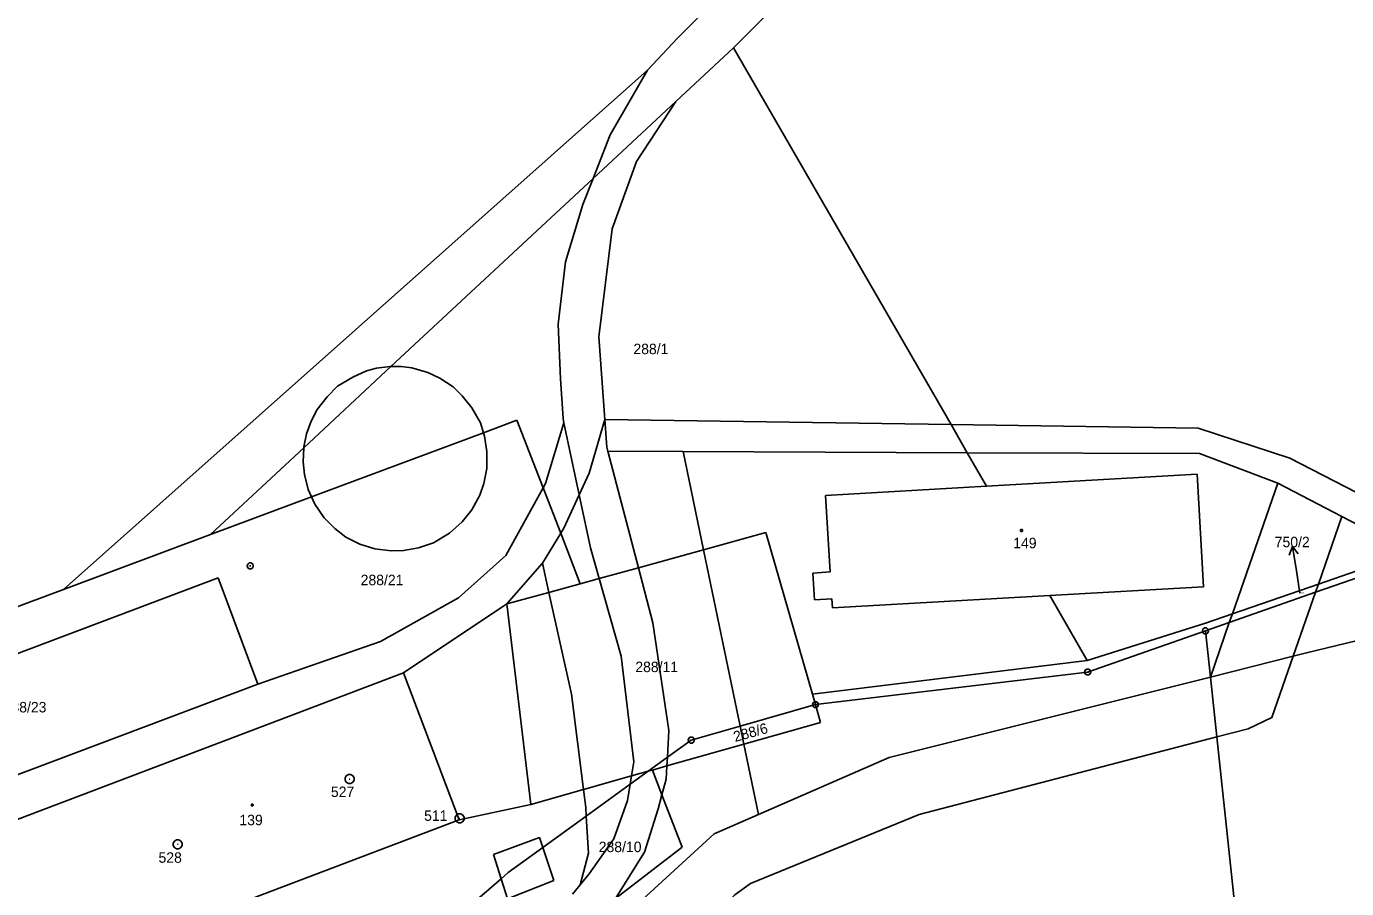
# Model space of a CAD drawing. Extents: x -694465 to -690527, y -983694 to -978978.
# Drawn here: x -693381.2 to -693166.5, y -981277 to -981137 of the extents above; entities that cross this region are included whole.
import ezdxf

# ---------------------------------------------------------------- set-up
doc = ezdxf.new("R2010")
doc.units = 0
for name, color, linetype in [('Vrstva 1', 7, 'Continuous'), ('Vrstva 16', 7, 'Continuous'), ('Vrstva 17', 7, 'Continuous'), ('Vrstva 18', 7, 'Continuous'), ('Vrstva 19', 7, 'Continuous'), ('Vrstva 24', 7, 'Continuous'), ('Vrstva 25', 7, 'Continuous'), ('Vrstva 29', 7, 'Continuous')]:
    doc.layers.add(name, color=color, linetype=linetype)

msp = doc.modelspace()

# ---------------------------------------------------------------- linework, layer by layer
at = {"layer": 'Vrstva 1'}
for points in [[(-693280.193, -981144.086), (-693275.377, -981138.931), (-693243.869, -981107.405), (-693240.17, -981100.71)], [(-693266.21, -981140.43), (-693233.406, -981107.461)], [(-693275.612, -981149.175), (-693266.21, -981140.43)], [(-693230.844, -981201.655), (-693266.21, -981140.43)], [(-693280.193, -981144.086), (-693375.15, -981228.43)], [(-693289.022, -981161.649), (-693286.252, -981154.594), (-693280.193, -981144.086)], [(-693289.022, -981161.649), (-693275.612, -981149.175)], [(-693287.127, -981200.804), (-693288.109, -981187.376), (-693285.917, -981169.842), (-693281.972, -981158.883), (-693275.612, -981149.175)], [(-693321.909, -981192.238), (-693289.022, -981161.649)], [(-693293.777, -981201.381), (-693293.927, -981200.67), (-693294.331, -981194.204), (-693294.735, -981185.312), (-693293.523, -981175.207), (-693290.696, -981165.911), (-693289.022, -981161.649)], [(-693336.077, -981205.416), (-693321.909, -981192.238)], [(-693325.879, -981192.903), (-693324.263, -981192.486), (-693322.057, -981192.239), (-693321.909, -981192.238)], [(-693321.909, -981192.238), (-693320.221, -981192.226), (-693318.482, -981192.41)], [(-693318.482, -981192.41), (-693315.906, -981193.178), (-693313.934, -981194.11), (-693311.797, -981195.535)], [(-693336.077, -981205.416), (-693336.071, -981205.294), (-693335.632, -981203.156), (-693334.865, -981201.073), (-693333.879, -981199.209), (-693332.29, -981197.125), (-693330.591, -981195.425), (-693328.126, -981193.945), (-693325.879, -981192.903)], [(-693311.797, -981195.535), (-693310.317, -981196.961), (-693308.728, -981198.934), (-693307.358, -981201.347), (-693306.869, -981202.981)], [(-693301.42, -981200.95), (-693306.869, -981202.981)], [(-693297.164, -981211.94), (-693301.42, -981200.95)], [(-693291.308, -981213.059), (-693289.7, -981209.56), (-693287.127, -981200.804)], [(-693230.844, -981201.655), (-693287.127, -981200.804)], [(-693286.625, -981205.993), (-693286.794, -981205.349), (-693287.127, -981200.804)], [(-693306.869, -981202.981), (-693334.805, -981213.394)], [(-693306.869, -981202.981), (-693306.701, -981203.54), (-693306.317, -981206.007), (-693306.317, -981208.803), (-693306.81, -981211.216), (-693307.468, -981213.135), (-693308.728, -981215.492), (-693310.317, -981217.466), (-693312.399, -981219.275), (-693314.975, -981220.865), (-693317.44, -981221.688), (-693319.851, -981222.126), (-693321.879, -981222.181), (-693324.509, -981221.852), (-693326.975, -981221.085), (-693329.221, -981219.933), (-693331.03, -981218.563), (-693332.783, -981216.808), (-693334.263, -981214.56), (-693334.805, -981213.394)], [(-693293.777, -981201.381), (-693296.77, -981211.226), (-693297.164, -981211.94)], [(-693291.308, -981213.059), (-693293.777, -981201.381)], [(-693228.204, -981206.224), (-693230.844, -981201.655)], [(-693152.637, -981218.409), (-693154.059, -981218.272), (-693175.759, -981207.087), (-693190.664, -981202.262), (-693230.844, -981201.655)], [(-693351.24, -981219.52), (-693336.077, -981205.416)], [(-693334.805, -981213.394), (-693335.358, -981212.203), (-693335.961, -981209.79), (-693336.18, -981207.707), (-693336.077, -981205.416)], [(-693274.382, -981206.042), (-693286.625, -981205.993)], [(-693281.676, -981224.918), (-693286.625, -981205.993)], [(-693228.204, -981206.224), (-693274.382, -981206.042)], [(-693274.382, -981206.042), (-693271.072, -981221.999)], [(-693225.07, -981211.65), (-693228.204, -981206.224)], [(-693190.444, -981206.373), (-693228.204, -981206.224)], [(-693190.444, -981206.373), (-693177.731, -981211.198)], [(-693251.23, -981213.15), (-693225.07, -981211.65)], [(-693190.81, -981209.69), (-693225.07, -981211.65)], [(-693189.77, -981228), (-693190.81, -981209.69)], [(-693177.731, -981211.198), (-693185.105, -981232.395)], [(-693177.731, -981211.198), (-693167.328, -981216.593)], [(-693334.805, -981213.394), (-693351.24, -981219.52)], [(-693297.164, -981211.94), (-693303.233, -981222.947), (-693310.908, -981229.818), (-693323.616, -981236.911), (-693343.52, -981243.82)], [(-693294.308, -981219.313), (-693297.164, -981211.94)], [(-693294.308, -981219.313), (-693293.808, -981218.5), (-693291.308, -981213.059)], [(-693288.07, -981226.678), (-693289.484, -981221.688), (-693291.308, -981213.059)], [(-693250.49, -981225.6), (-693251.23, -981213.15)], [(-693171.118, -981227.562), (-693167.328, -981216.593)], [(-693167.328, -981216.593), (-693156.15, -981222.39)], [(-693351.24, -981219.52), (-693375.15, -981228.43)], [(-693297.288, -981224.155), (-693294.308, -981219.313)], [(-693291.13, -981227.52), (-693294.308, -981219.313)], [(-693260.94, -981219.21), (-693271.072, -981221.999)], [(-693253.37, -981245.45), (-693260.94, -981219.21)], [(-693271.072, -981221.999), (-693281.676, -981224.918)], [(-693271.072, -981221.999), (-693265.13, -981250.647)], [(-693156.15, -981222.39), (-693171.118, -981227.562)], [(-693303.05, -981230.8), (-693297.315, -981224.198), (-693297.288, -981224.155)], [(-693296.229, -981228.923), (-693297.288, -981224.155)], [(-693171.597, -981228.897), (-693155.44, -981223.28)], [(-693405.77, -981247.58), (-693350.01, -981226.58)], [(-693350.01, -981226.58), (-693343.52, -981243.82)], [(-693288.07, -981226.678), (-693291.13, -981227.52)], [(-693281.676, -981224.918), (-693288.07, -981226.678)], [(-693282.787, -981258.751), (-693282.415, -981256.447), (-693284.499, -981239.282), (-693288.07, -981226.678)], [(-693276.953, -981255.718), (-693276.712, -981251.376), (-693279.342, -981233.842), (-693281.676, -981224.918)], [(-693253.29, -981225.77), (-693250.49, -981225.6)], [(-693253.04, -981230.14), (-693253.29, -981225.77)], [(-693375.15, -981228.43), (-693413.16, -981242.59)], [(-693296.229, -981228.923), (-693303.05, -981230.8)], [(-693291.13, -981227.52), (-693296.229, -981228.923)], [(-693290.598, -981260.957), (-693292.562, -981245.435), (-693296.229, -981228.923)], [(-693214.8, -981229.43), (-693189.77, -981228)], [(-693185.603, -981233.825), (-693171.597, -981228.897)], [(-693171.118, -981227.562), (-693185.105, -981232.395)], [(-693175.202, -981239.29), (-693171.597, -981228.897)], [(-693171.597, -981228.897), (-693171.118, -981227.562)], [(-693303.05, -981230.8), (-693319.84, -981241.99)], [(-693303.05, -981230.8), (-693299.18, -981263.38)], [(-693250.23, -981229.97), (-693253.04, -981230.14)], [(-693250.14, -981231.44), (-693250.23, -981229.97)], [(-693214.8, -981229.43), (-693250.14, -981231.44)], [(-693208.69, -981240.01), (-693214.8, -981229.43)], [(-693173.05, -981238.75), (-693137.37, -981230.15)], [(-693185.105, -981232.395), (-693189.46, -981233.9)], [(-693185.105, -981232.395), (-693185.603, -981233.825)], [(-693189.46, -981233.9), (-693208.69, -981240.01)], [(-693208.63, -981241.86), (-693189.48, -981235.18)], [(-693189.48, -981235.18), (-693185.603, -981233.825)], [(-693189.48, -981235.18), (-693188.68, -981242.67)], [(-693185.603, -981233.825), (-693188.68, -981242.67)], [(-693188.68, -981242.67), (-693175.202, -981239.29)], [(-693187.639, -981252.397), (-693182.55, -981251.063), (-693178.661, -981249.232), (-693175.202, -981239.29)], [(-693175.202, -981239.29), (-693173.05, -981238.75)], [(-693208.69, -981240.01), (-693253.37, -981245.45)], [(-693343.52, -981243.82), (-693399.28, -981264.81)], [(-693396.71, -981271.14), (-693319.84, -981241.99)], [(-693319.84, -981241.99), (-693310.8, -981265.85)], [(-693252.88, -981247.15), (-693208.63, -981241.86)], [(-693240.91, -981255.75), (-693188.68, -981242.67)], [(-693188.68, -981242.67), (-693187.639, -981252.397)], [(-693253.37, -981245.45), (-693252.88, -981247.15)], [(-693265.13, -981250.647), (-693252.88, -981247.15)], [(-693252.04, -981250.06), (-693252.88, -981247.15)], [(-693264.521, -981253.587), (-693252.04, -981250.06)], [(-693283.73, -981293.672), (-693275.124, -981286.967), (-693265.973, -981278.041), (-693263.457, -981276.21), (-693236.006, -981264.995), (-693187.639, -981252.397)], [(-693273.09, -981252.92), (-693265.13, -981250.647)], [(-693265.13, -981250.647), (-693264.521, -981253.587)], [(-693187.639, -981252.397), (-693180.786, -981316.433)], [(-693277.031, -981257.123), (-693264.521, -981253.587)], [(-693276.953, -981255.718), (-693273.09, -981252.92)], [(-693264.521, -981253.587), (-693262.149, -981265.022)], [(-693280.09, -981257.99), (-693276.953, -981255.718)], [(-693277.031, -981257.123), (-693276.953, -981255.718)], [(-693262.149, -981265.022), (-693240.91, -981255.75)], [(-693290.598, -981260.957), (-693282.787, -981258.751)], [(-693280.09, -981257.99), (-693283.004, -981260.099)], [(-693283.004, -981260.099), (-693282.787, -981258.751)], [(-693282.787, -981258.751), (-693280.09, -981257.99)], [(-693279.39, -981257.79), (-693280.09, -981257.99)], [(-693279.39, -981257.79), (-693277.031, -981257.123)], [(-693277.839, -981261.792), (-693279.39, -981257.79)], [(-693277.839, -981261.792), (-693277.15, -981259.267), (-693277.031, -981257.123)], [(-693299.18, -981263.38), (-693290.598, -981260.957)], [(-693291.14, -981276.413), (-693289.686, -981274.635), (-693285.647, -981268.976), (-693283.425, -981262.711), (-693283.004, -981260.099)], [(-693290.144, -981265.266), (-693290.232, -981263.849), (-693290.598, -981260.957)], [(-693283.004, -981260.099), (-693290.144, -981265.266)], [(-693285.41, -981278.66), (-693280.657, -981271.103), (-693278.465, -981264.089), (-693277.839, -981261.792)], [(-693274.54, -981270.3), (-693277.839, -981261.792)], [(-693310.8, -981265.85), (-693299.18, -981263.38)], [(-693290.144, -981265.266), (-693297.21, -981270.38)], [(-693291.14, -981276.413), (-693289.767, -981271.308), (-693290.144, -981265.266)], [(-693269.36, -981268.17), (-693262.149, -981265.022)], [(-693310.8, -981265.85), (-693387.67, -981294.99)], [(-693305.25, -981271.53), (-693297.76, -981268.73)], [(-693297.76, -981268.73), (-693297.21, -981270.38)], [(-693284.98, -981282.47), (-693269.36, -981268.17)], [(-693305.25, -981271.53), (-693303.98, -981275.44)], [(-693297.21, -981270.38), (-693302.83, -981274.45)], [(-693295.44, -981275.74), (-693297.21, -981270.38)], [(-693285.41, -981278.66), (-693274.54, -981270.3)], [(-693303.98, -981275.44), (-693323.14, -981291.95)], [(-693302.83, -981274.45), (-693303.98, -981275.44)], [(-693302.93, -981278.7), (-693303.98, -981275.44)], [(-693295.44, -981275.74), (-693302.93, -981278.7)], [(-693292.41, -981277.965), (-693291.14, -981276.413)]]:
    msp.add_lwpolyline(points, dxfattribs=at)
at = {"layer": 'Vrstva 16'}
msp.add_line((-693174.13, -981229.06), (-693174.7, -981225.44), dxfattribs=at)
at = {"layer": 'Vrstva 24'}
for points in [[(-693344.636, -981224.134), (-693344.386, -981224.316), (-693344.29, -981224.61), (-693344.386, -981224.904), (-693344.636, -981225.086), (-693344.944, -981225.086), (-693345.194, -981224.904), (-693345.29, -981224.61), (-693345.194, -981224.316), (-693344.944, -981224.134)], [(-693189.326, -981234.704), (-693189.076, -981234.886), (-693188.98, -981235.18), (-693189.076, -981235.474), (-693189.326, -981235.656), (-693189.634, -981235.656), (-693189.884, -981235.474), (-693189.98, -981235.18), (-693189.884, -981234.886), (-693189.634, -981234.704)], [(-693208.476, -981241.384), (-693208.226, -981241.566), (-693208.13, -981241.86), (-693208.226, -981242.154), (-693208.476, -981242.336), (-693208.784, -981242.336), (-693209.034, -981242.154), (-693209.13, -981241.86), (-693209.034, -981241.566), (-693208.784, -981241.384)], [(-693252.726, -981246.674), (-693252.476, -981246.856), (-693252.38, -981247.15), (-693252.476, -981247.444), (-693252.726, -981247.626), (-693253.034, -981247.626), (-693253.284, -981247.444), (-693253.38, -981247.15), (-693253.284, -981246.856), (-693253.034, -981246.674)], [(-693272.936, -981252.444), (-693272.686, -981252.626), (-693272.59, -981252.92), (-693272.686, -981253.214), (-693272.936, -981253.396), (-693273.244, -981253.396), (-693273.494, -981253.214), (-693273.59, -981252.92), (-693273.494, -981252.626), (-693273.244, -981252.444)], [(-693328.436, -981258.526), (-693328.1, -981258.72), (-693327.906, -981259.056), (-693327.906, -981259.444), (-693328.1, -981259.78), (-693328.436, -981259.974), (-693328.824, -981259.974), (-693329.16, -981259.78), (-693329.354, -981259.444), (-693329.354, -981259.056), (-693329.16, -981258.72), (-693328.824, -981258.526)], [(-693310.546, -981264.916), (-693310.21, -981265.11), (-693310.016, -981265.446), (-693310.016, -981265.834), (-693310.21, -981266.17), (-693310.546, -981266.364), (-693310.934, -981266.364), (-693311.27, -981266.17), (-693311.464, -981265.834), (-693311.464, -981265.446), (-693311.27, -981265.11), (-693310.934, -981264.916)], [(-693356.376, -981269.126), (-693356.04, -981269.32), (-693355.846, -981269.656), (-693355.846, -981270.044), (-693356.04, -981270.38), (-693356.376, -981270.574), (-693356.764, -981270.574), (-693357.1, -981270.38), (-693357.294, -981270.044), (-693357.294, -981269.656), (-693357.1, -981269.32), (-693356.764, -981269.126)]]:
    msp.add_lwpolyline(points, close=True, dxfattribs=at)
for points in [[(-693344.909, -981224.61), (-693344.67, -981224.61)], [(-693189.599, -981235.18), (-693189.36, -981235.18)], [(-693208.749, -981241.86), (-693208.51, -981241.86)], [(-693252.999, -981247.15), (-693252.76, -981247.15)], [(-693273.209, -981252.92), (-693272.97, -981252.92)], [(-693328.68, -981259.25), (-693328.58, -981259.25)], [(-693310.79, -981265.64), (-693310.69, -981265.64)], [(-693356.62, -981269.85), (-693356.52, -981269.85)]]:
    msp.add_lwpolyline(points, dxfattribs=at)
at = {"layer": 'Vrstva 25'}
for points in [[(-693219.293, -981218.698), (-693219.205, -981218.85), (-693219.293, -981219.002), (-693219.467, -981219.002), (-693219.555, -981218.85), (-693219.467, -981218.698)], [(-693344.373, -981263.308), (-693344.285, -981263.46), (-693344.373, -981263.612), (-693344.547, -981263.612), (-693344.635, -981263.46), (-693344.547, -981263.308)]]:
    msp.add_lwpolyline(points, close=True, dxfattribs=at)
at = {"layer": 'Vrstva 29'}
for points in [[(-693174.7, -981225.44), (-693175.325, -981221.489), (-693175.863, -981222.89)], [(-693174.381, -981222.656), (-693175.325, -981221.489)]]:
    msp.add_lwpolyline(points, dxfattribs=at)

# ---------------------------------------------------------------- texts
at = {"layer": 'Vrstva 16'}
msp.add_text('750/2', height=1.7, dxfattribs=at).set_placement((-693178.213, -981221.58))
at = {"layer": 'Vrstva 17'}
for s, p in [('527', (-693331.663, -981262.17)), ('511', (-693316.514, -981266.04)), ('528', (-693359.693, -981272.85))]:
    msp.add_text(s, height=1.7, dxfattribs=at).set_placement(p)
at = {"layer": 'Vrstva 18'}
for s, height, p in [('288/1', 1.7, (-693282.482, -981190.21)), ('288/21', 1.7, (-693326.823, -981227.75)), ('750/2', 0.2, (-693174.102, -981229.06)), ('288/11', 1.7, (-693282.173, -981241.87)), ('288/23', 1.7, (-693384.87, -981248.42)), ('288/10', 1.7, (-693288.123, -981271.12))]:
    msp.add_text(s, height=height, dxfattribs=at).set_placement(p)
msp.add_text('288/6', height=1.7, rotation=15.41256, dxfattribs=at).set_placement((-693265.952, -981253.236))
at = {"layer": 'Vrstva 19'}
for s, p in [('149', (-693220.727, -981221.75)), ('139', (-693346.543, -981266.75))]:
    msp.add_text(s, height=1.7, dxfattribs=at).set_placement(p)

doc.saveas('drawing.dxf')
